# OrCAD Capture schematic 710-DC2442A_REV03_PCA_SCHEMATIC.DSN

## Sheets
1 PAGE4: note: LOW STRESS STAGED START 200A HOT SWAP CONTROLLER
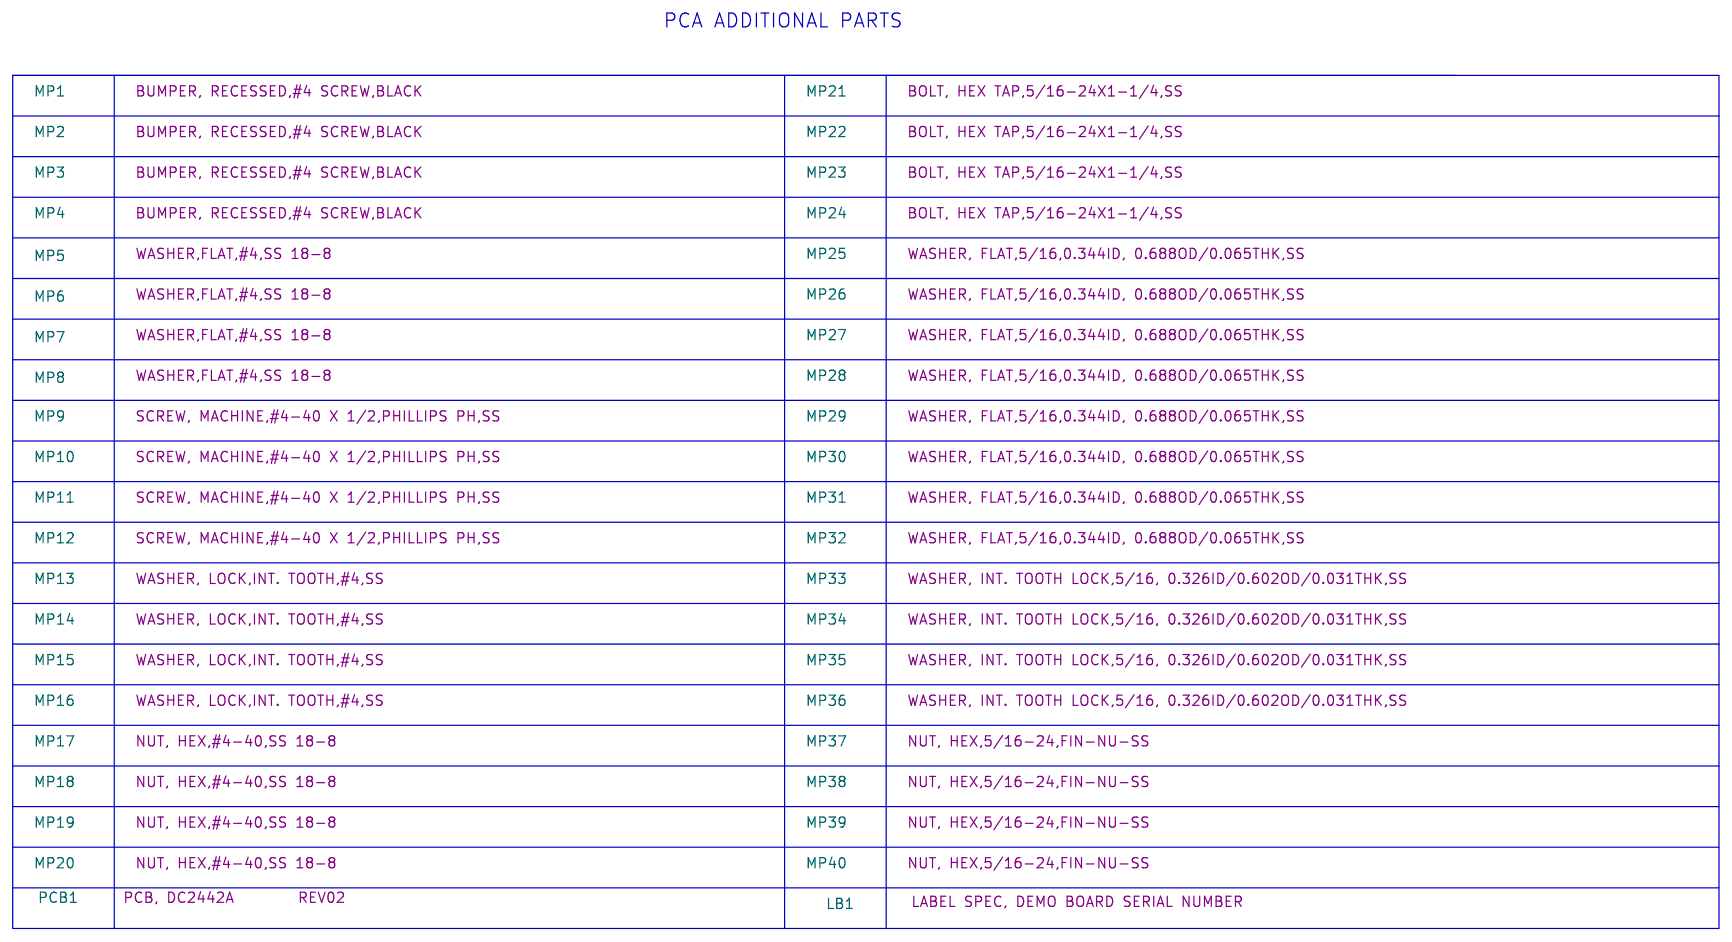
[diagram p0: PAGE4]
2 PAGE3: size Custom
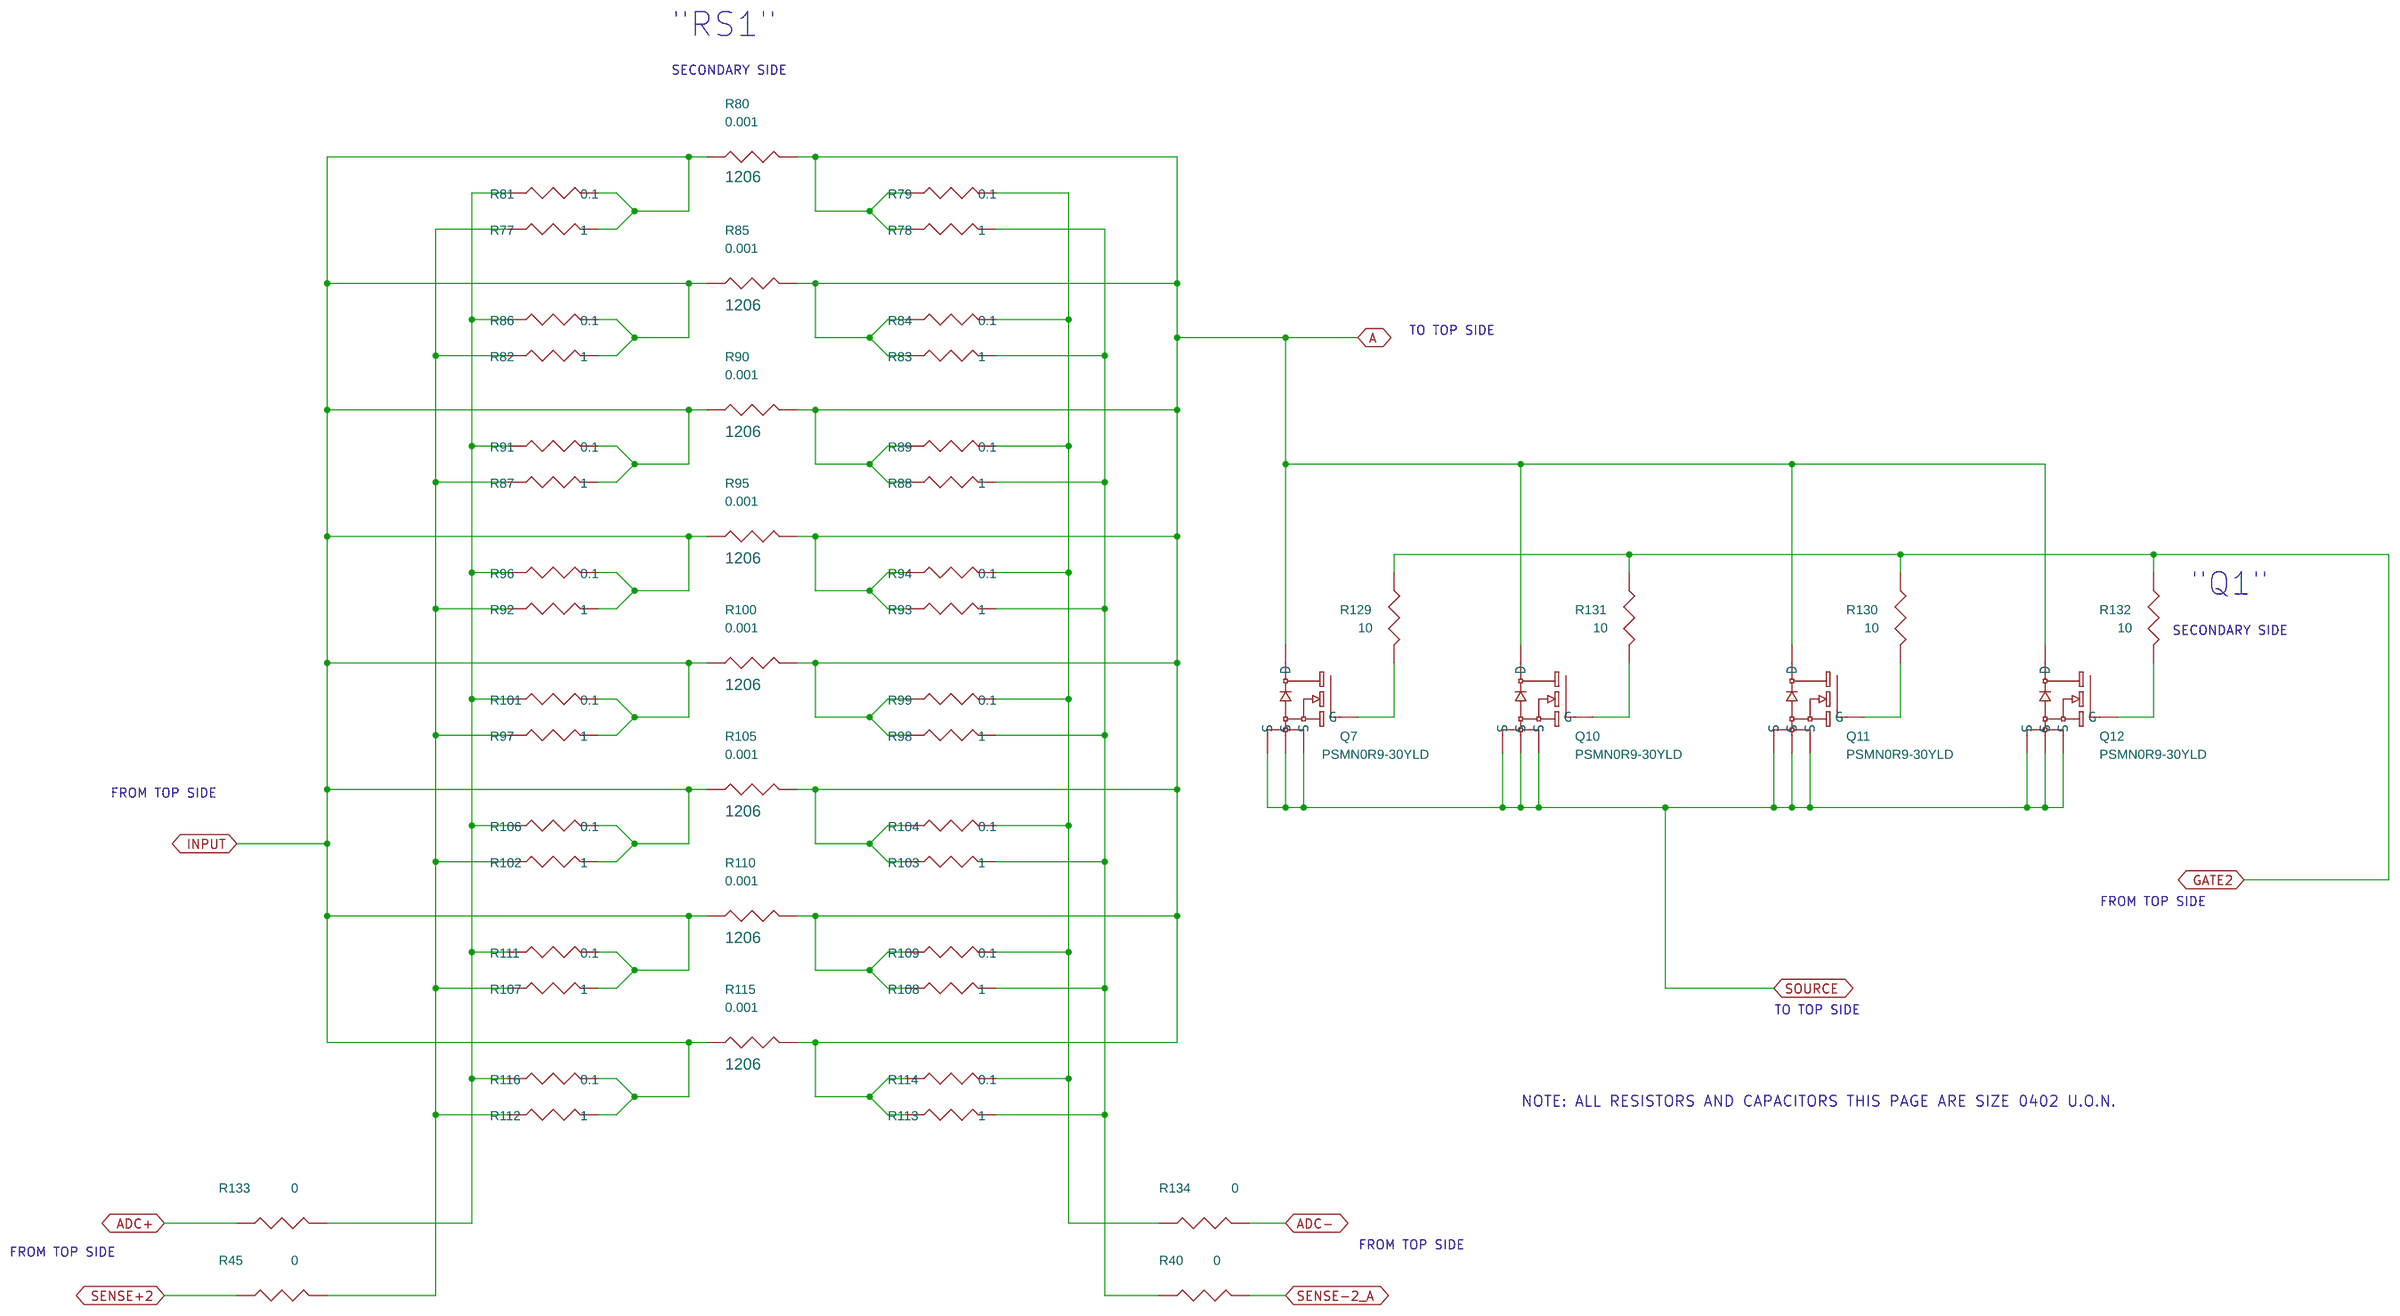
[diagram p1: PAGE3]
3 PAGE1: size Custom
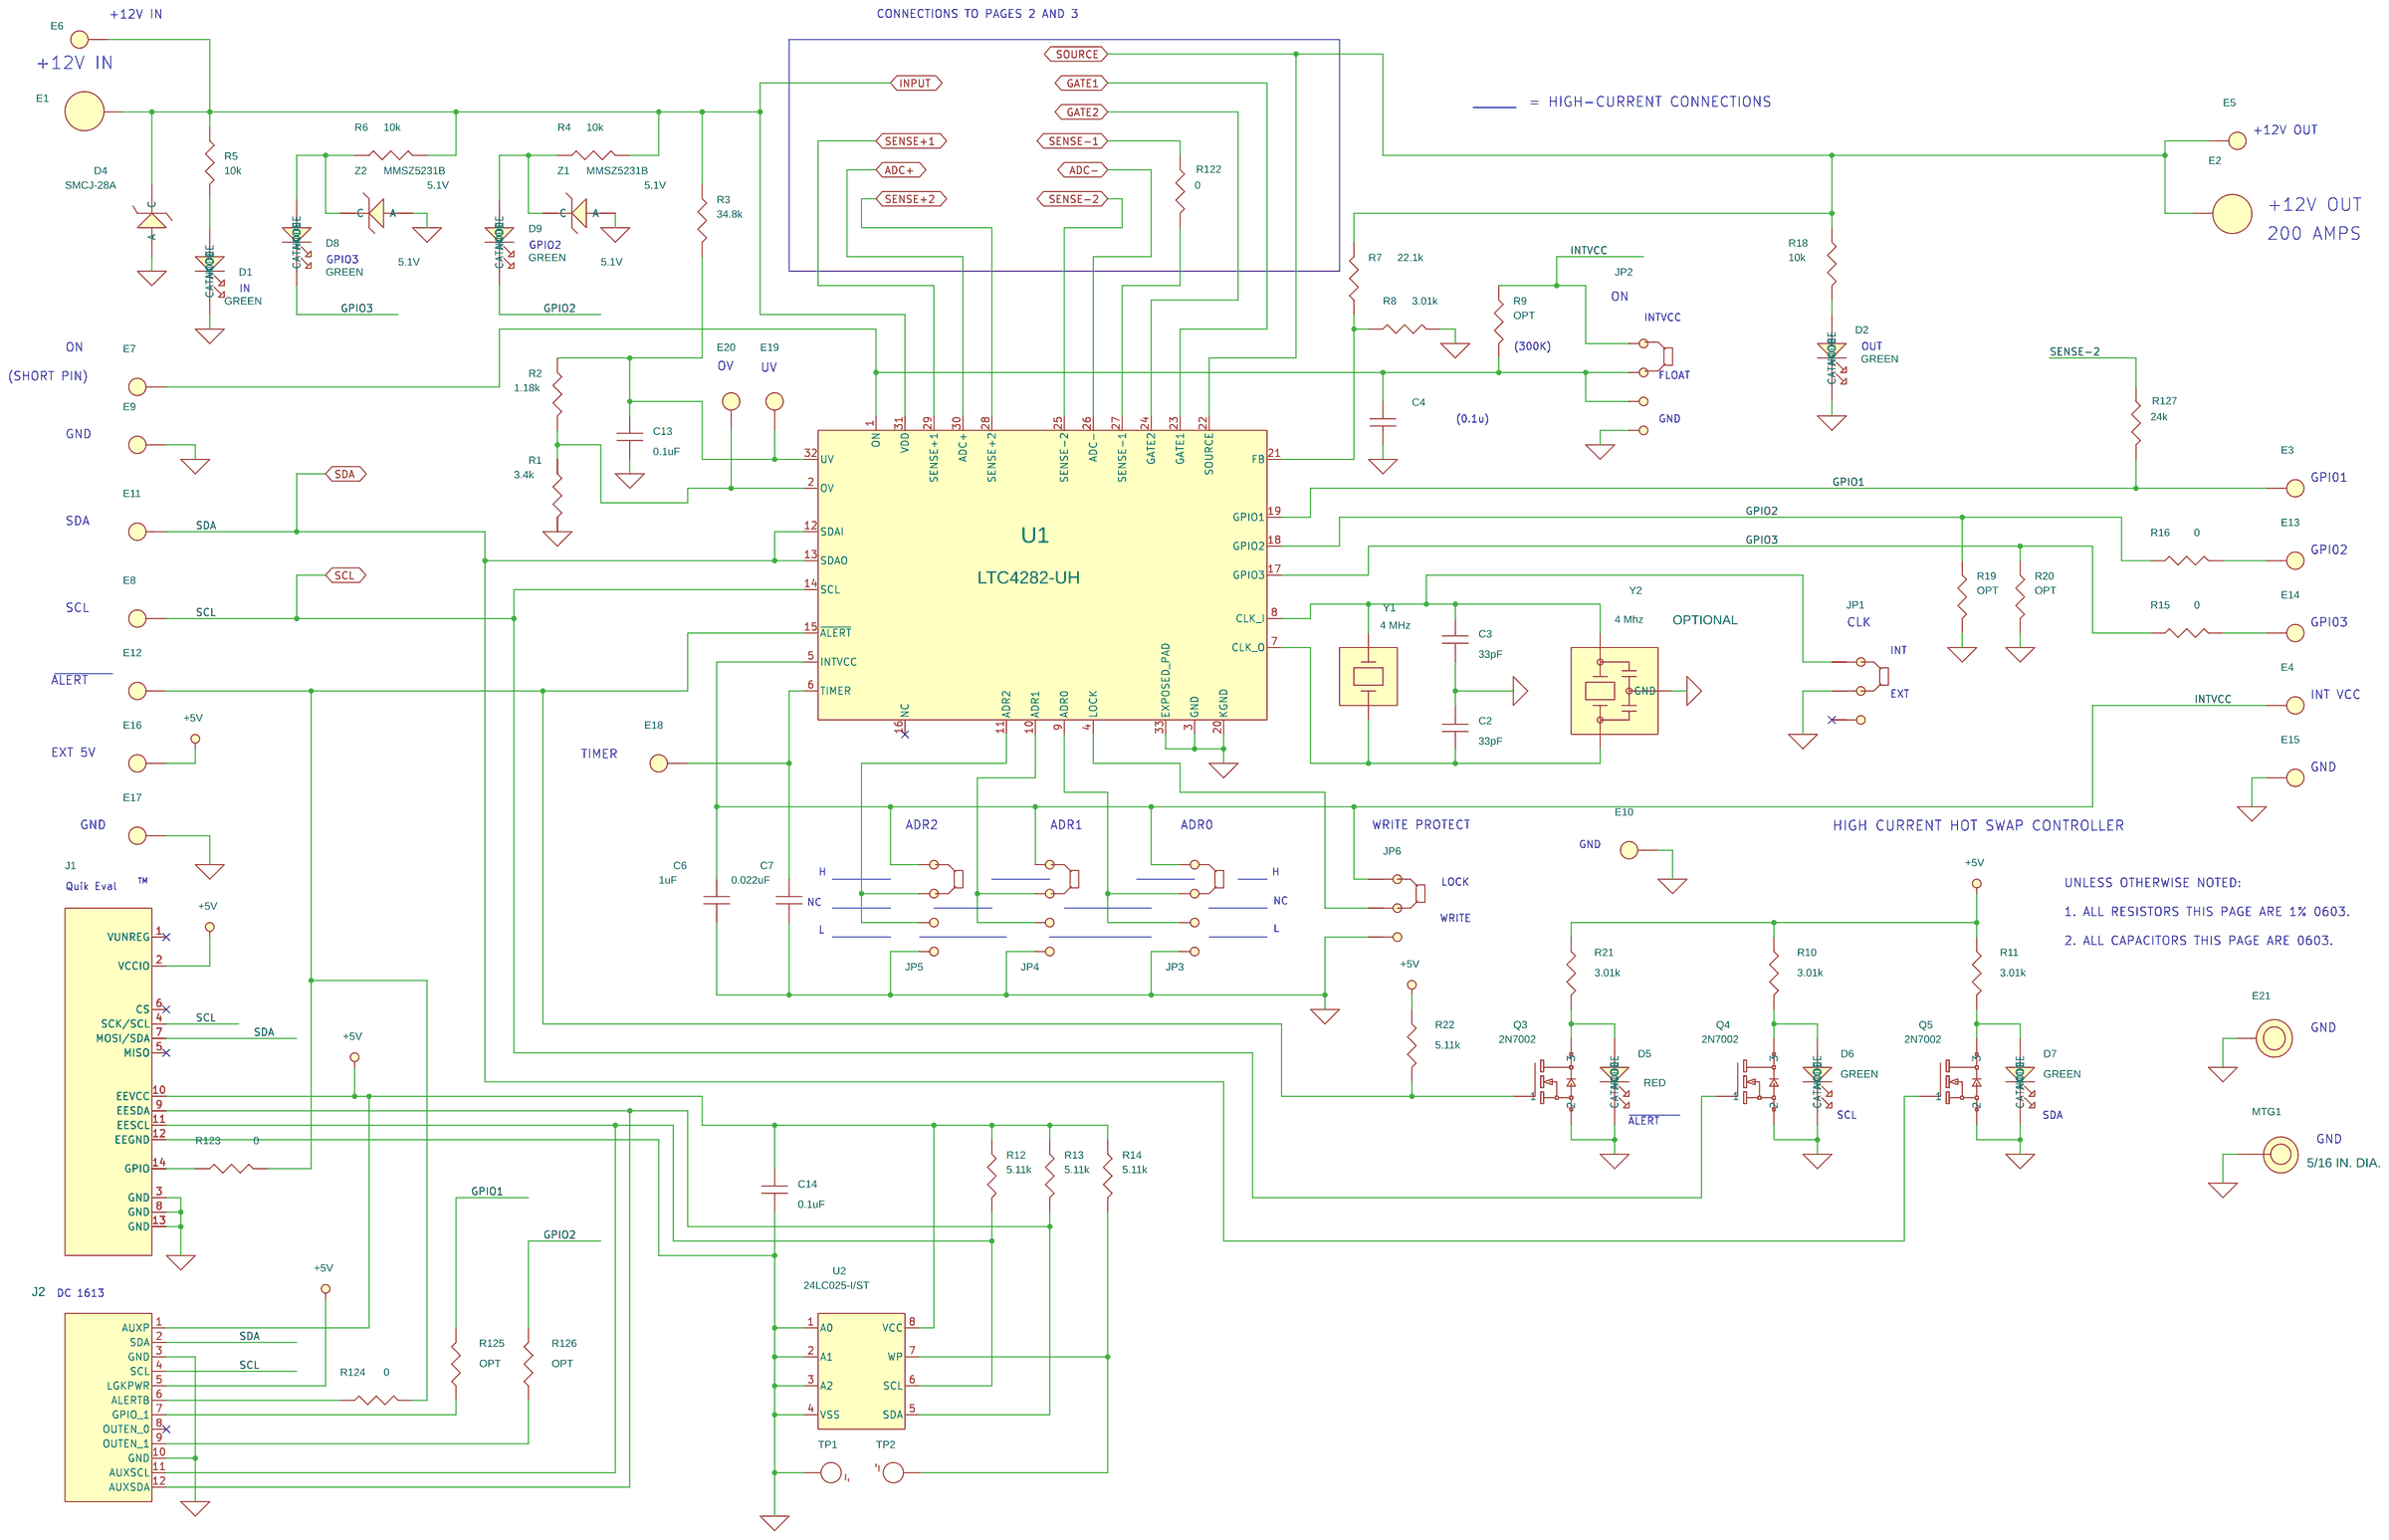
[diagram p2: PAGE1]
4 PAGE2: size Custom
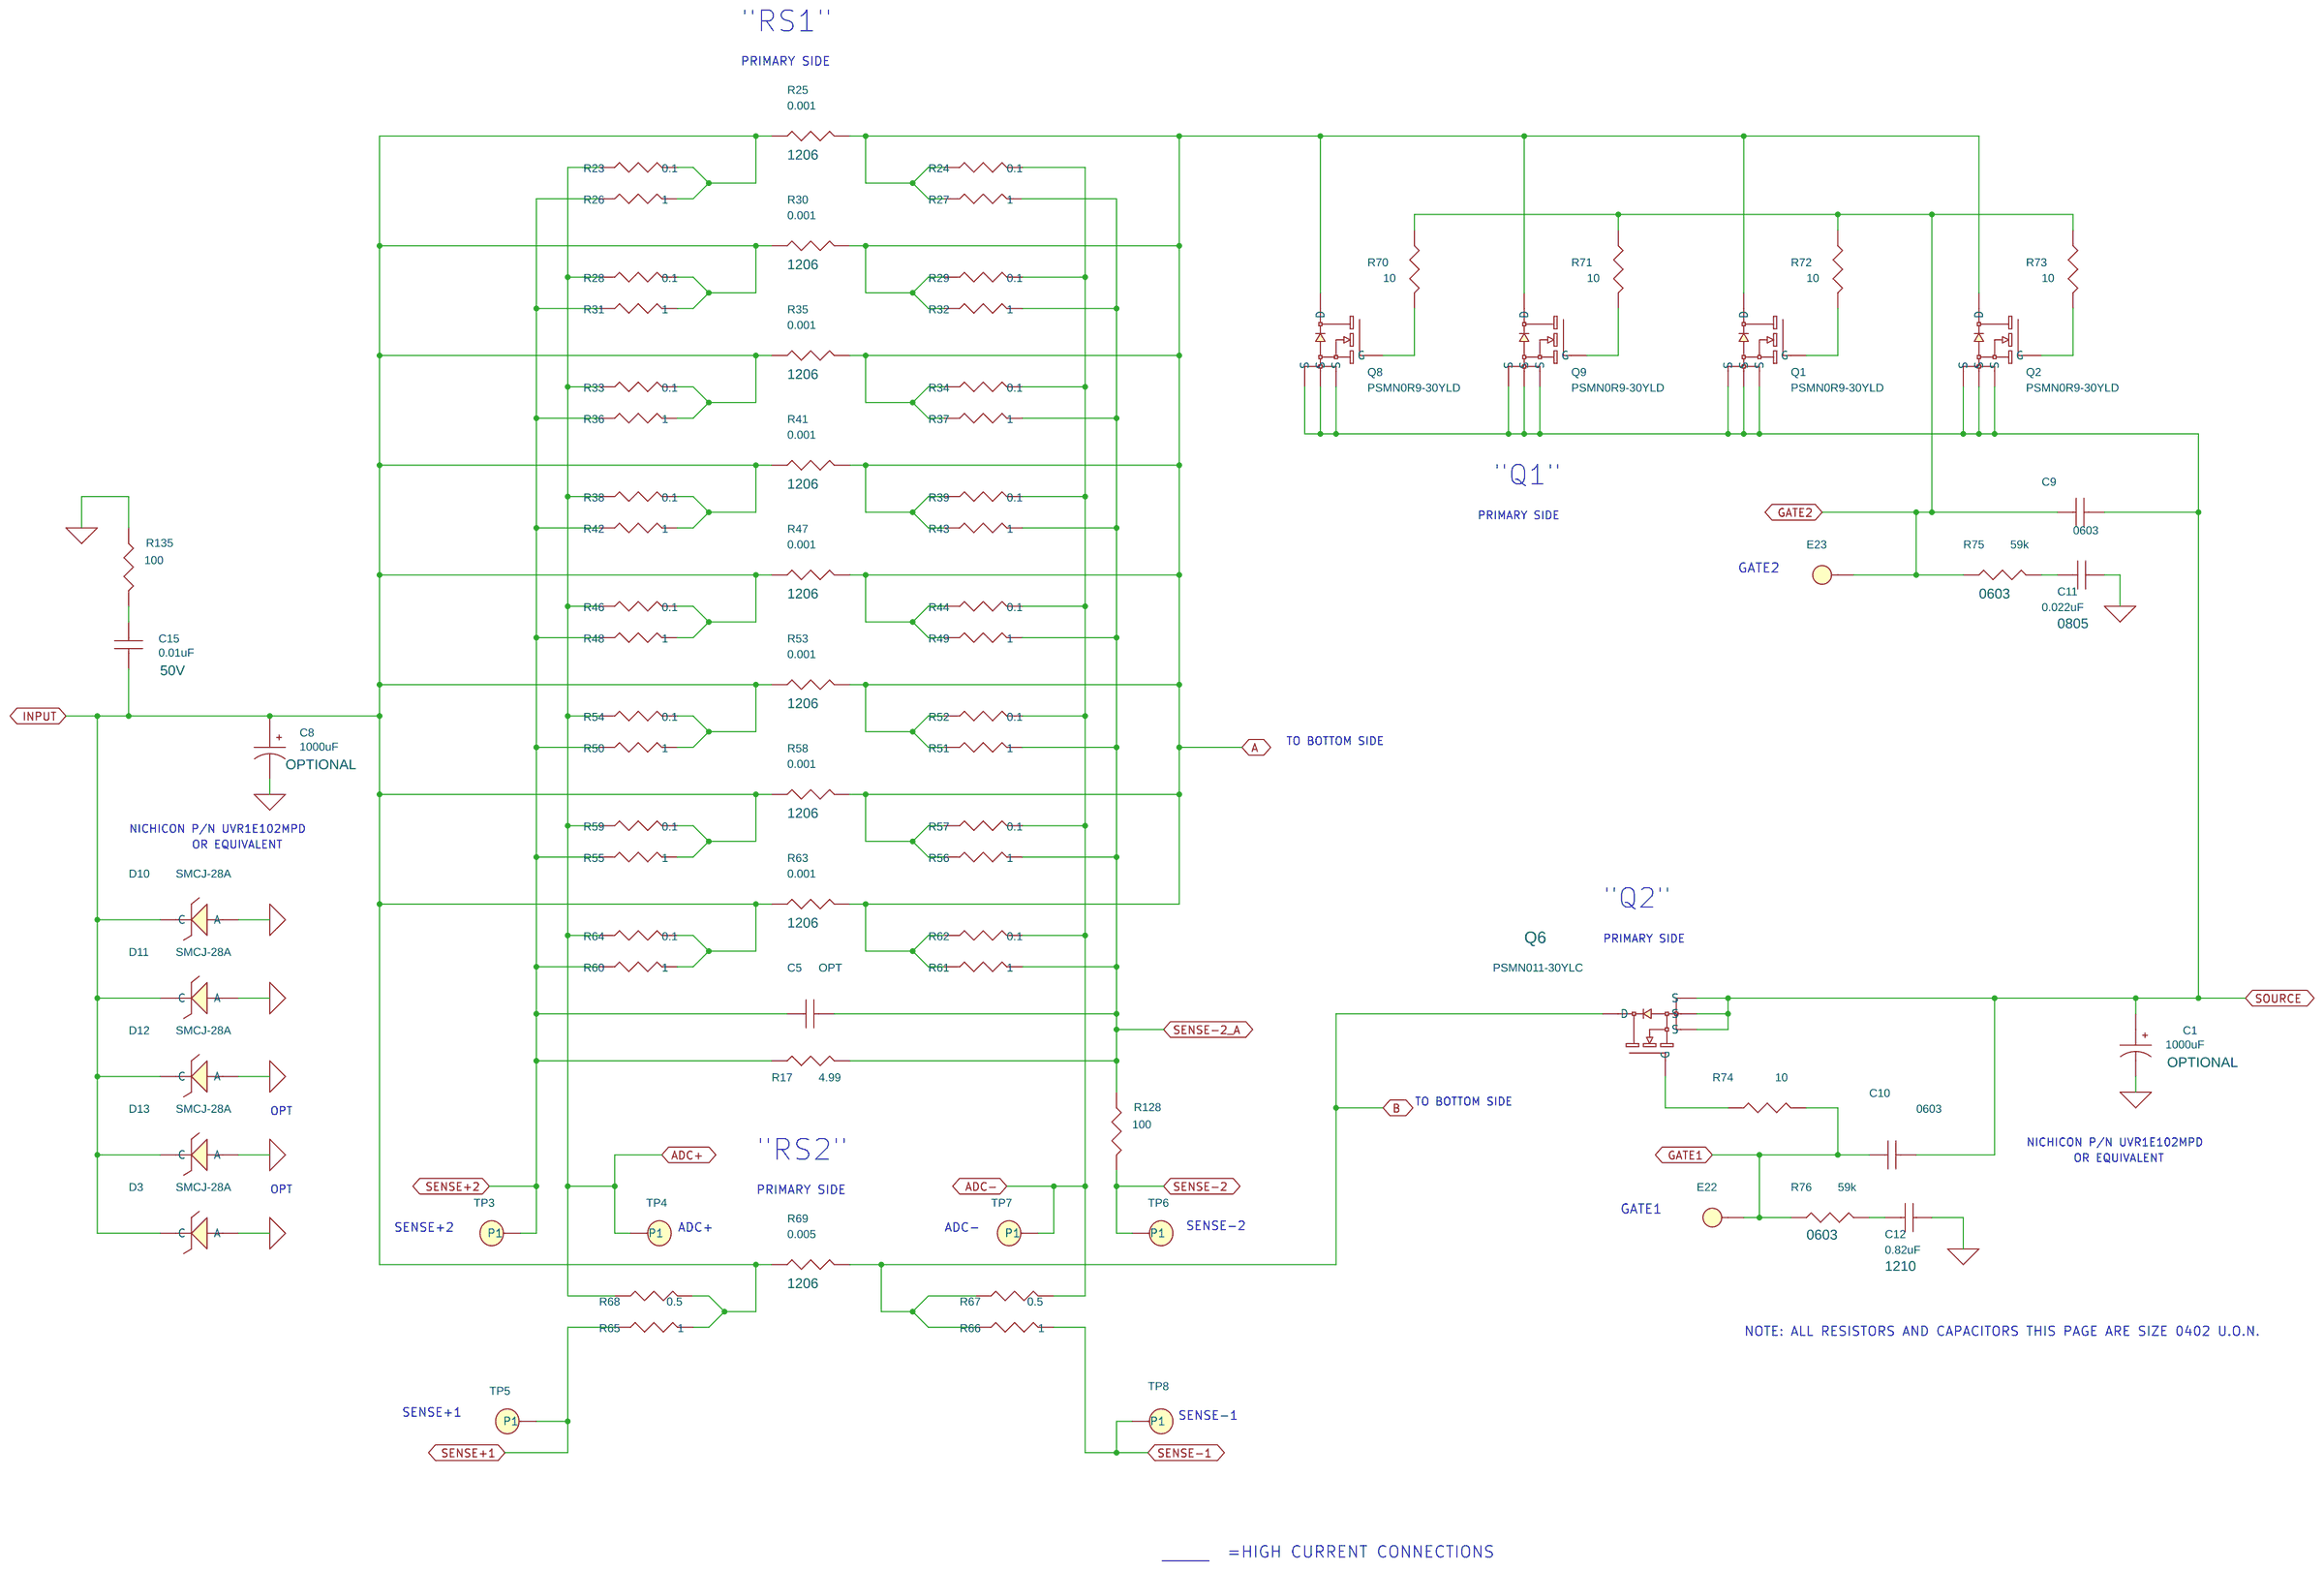
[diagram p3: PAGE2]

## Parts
sheet PAGE1
C2  33pF  [CC0603N]
C3  33pF  [CC0603N]
C4  OPT  [CC0603N]
C6  1uF  [CC0603N]
C7  0.022uF  [CC0603N]
C13  0.1uF  [CC0603N]
C14  0.1uF  [CC0603N]
D1  GREEN  [LED_0805]
D2  GREEN  [LED_0805]
D4  SMCJ-28A  [DIODESINC-SMC]
D5  RED  [LED_0805]
D6  GREEN  [LED_0805]
D7  GREEN  [LED_0805]
D8  GREEN  [LED_0805]
D9  GREEN  [LED_0805]
E1  LUG  [CO225-56HK-QY]
E2  LUG  [CO225-56HK-QY]
E3  TEST POINT  [MILLMAX2308]
E4  TEST POINT  [MILLMAX2308]
E5  TEST POINT  [MILLMAX2308]
E6  TEST POINT  [MILLMAX2308]
E7  TEST POINT  [MILLMAX2308]
E8  TEST POINT  [MILLMAX2308]
E9  TEST POINT  [MILLMAX2308]
E10  TEST POINT  [MILLMAX2308]
E11  TEST POINT  [MILLMAX2308]
E12  TEST POINT  [MILLMAX2308]
E13  TEST POINT  [MILLMAX2308]
E14  TEST POINT  [MILLMAX2308]
E15  TEST POINT  [MILLMAX2308]
E16  TEST POINT  [MILLMAX2308]
E17  TEST POINT  [MILLMAX2308]
E18  TEST POINT  [MILLMAX2308]
E19  TEST POINT  [MILLMAX2308]
E20  TEST POINT  [MILLMAX2308]
E21  BANANA JACK  [KEY-575-4]
J1  HDR.  [HD2X7-079-MOLEX]
J2  HDR, SHROUDED  [HD2X6-079-MOLEX]
JP1  HDR.  [JP3X1/079]
JP2  HDR.  [JP4X1/079]
JP3  HDR.  [JP4X1/079]
JP4  HDR.  [JP4X1/079]
JP5  HDR.  [JP4X1/079]
JP6  HDR.  [JP3X1/079]
MTG1  MTG HOLE  [MTG_5/16]
Q3  2N7002  [SOT23-3N]
Q4  2N7002  [SOT23-3N]
Q5  2N7002  [SOT23-3N]
R1  3.4k  [CR0603N]
R2  1.18k  [CR0603N]
R3  34.8k  [CR0603N]
R4  10k  [CR1206N]
R5  10k  [CR1206N]
R6  10k  [CR1206N]
R7  22.1k  [CR0603N]
R8  3.01k  [CR0603N]
R9  OPT  [CR0603N]
R10  3.01k  [CR0603N]
R11  3.01k  [CR0603N]
R12  5.11k  [CR0603N]
R13  5.11k  [CR0603N]
R14  5.11k  [CR0603N]
R15  0  [CR0603N]
R16  0  [CR0603N]
R18  10k  [CR1206N]
R19  OPT  [CR0603N]
R20  OPT  [CR0603N]
R21  3.01k  [CR0603N]
R22  5.11k  [CR0603N]
R122  0  [CR0603N]
R123  0  [CR0603N]
R124  0  [CR0603N]
R125  OPT  [CR0603N]
R126  OPT  [CR0603N]
R127  24k  [CR0603N]
TP1  TEST PAD  [PADSTYLE6]
TP2  TEST PAD  [PADSTYLE6]
U1  LTC4282-UH  [LTC-UH-32-1693]
U2  24LC025-I/ST  [MICROCHIP-TSSOP-8]
XJP1  SHUNT
XJP2  SHUNT
XJP3  SHUNT
XJP4  SHUNT
XJP5  SHUNT
XJP6  SHUNT
Y1  4 MHz  [ABRACON-ABLS]
Y2  4 Mhz  [MURATA-CSTCR_G]
Z1  MMSZ5231B  [SOD-123N]
Z2  MMSZ5231B  [SOD-123N]
sheet PAGE2
C1  1000uF  [CAPRD10H20LS5]
C5  OPT  [CC0402N]
C8  1000uF  [CAPRD10H20LS5]
C9  OPT  [CC0603N]
C10  OPT  [CC0603N]
C11  0.022uF  [CC0805N]
C12  0.82uF  [CC1210N]
C15  0.01uF  [CC0603N]
D3  SMCJ-28A  [DIODESINC-SMC]
D10  SMCJ-28A  [DIODESINC-SMC]
D11  SMCJ-28A  [DIODESINC-SMC]
D12  SMCJ-28A  [DIODESINC-SMC]
D13  SMCJ-28A  [DIODESINC-SMC]
E22  TEST POINT  [MILLMAX2308]
E23  TEST POINT  [MILLMAX2308]
Q1  PSMN0R9-30YLD  [NXP-LFPAK56]
Q2  PSMN0R9-30YLD  [NXP-LFPAK56]
Q6  PSMN011-30YLC  [NXP-LFPAK(SOT669)]
Q8  PSMN0R9-30YLD  [NXP-LFPAK56]
Q9  PSMN0R9-30YLD  [NXP-LFPAK56]
R17  4.99  [CR0402N]
R23  0.1  [CR0402N]
R24  0.1  [CR0402N]
R25  0.001  [VISHAY_WSL1206]
R26  1  [CR0402N]
R27  1  [CR0402N]
R28  0.1  [CR0402N]
R29  0.1  [CR0402N]
R30  0.001  [VISHAY_WSL1206]
R31  1  [CR0402N]
R32  1  [CR0402N]
R33  0.1  [CR0402N]
R34  0.1  [CR0402N]
R35  0.001  [VISHAY_WSL1206]
R36  1  [CR0402N]
R37  1  [CR0402N]
R38  0.1  [CR0402N]
R39  0.1  [CR0402N]
R41  0.001  [VISHAY_WSL1206]
R42  1  [CR0402N]
R43  1  [CR0402N]
R44  0.1  [CR0402N]
R46  0.1  [CR0402N]
R47  0.001  [VISHAY_WSL1206]
R48  1  [CR0402N]
R49  1  [CR0402N]
R50  1  [CR0402N]
R51  1  [CR0402N]
R52  0.1  [CR0402N]
R53  0.001  [VISHAY_WSL1206]
R54  0.1  [CR0402N]
R55  1  [CR0402N]
R56  1  [CR0402N]
R57  0.1  [CR0402N]
R58  0.001  [VISHAY_WSL1206]
R59  0.1  [CR0402N]
R60  1  [CR0402N]
R61  1  [CR0402N]
R62  0.1  [CR0402N]
R63  0.001  [VISHAY_WSL1206]
R64  0.1  [CR0402N]
R65  1  [CR0402N]
R66  1  [CR0402N]
R67  0.5  [CR0402N]
R68  0.5  [CR0402N]
R69  0.005  [VISHAY_WSL1206]
R70  10  [CR0402N]
R71  10  [CR0402N]
R72  10  [CR0402N]
R73  10  [CR0402N]
R74  10  [CR0402N]
R75  59k  [CR0603N]
R76  59k  [CR0603N]
R128  100  [CR0402N]
R135  100  [CR0603N]
TP3  TEST PAD  [PADSTYLE2]
TP4  TEST PAD  [PADSTYLE2]
TP5  TEST PAD  [PADSTYLE2]
TP6  TEST PAD  [PADSTYLE2]
TP7  TEST PAD  [PADSTYLE2]
TP8  TEST PAD  [PADSTYLE2]
sheet PAGE3
Q7  PSMN0R9-30YLD  [NXP-LFPAK56]
Q10  PSMN0R9-30YLD  [NXP-LFPAK56]
Q11  PSMN0R9-30YLD  [NXP-LFPAK56]
Q12  PSMN0R9-30YLD  [NXP-LFPAK56]
R40  0  [CR0402N]
R45  0  [CR0402N]
R77  1  [CR0402N]
R78  1  [CR0402N]
R79  0.1  [CR0402N]
R80  0.001  [VISHAY_WSL1206]
R81  0.1  [CR0402N]
R82  1  [CR0402N]
R83  1  [CR0402N]
R84  0.1  [CR0402N]
R85  0.001  [VISHAY_WSL1206]
R86  0.1  [CR0402N]
R87  1  [CR0402N]
R88  1  [CR0402N]
R89  0.1  [CR0402N]
R90  0.001  [VISHAY_WSL1206]
R91  0.1  [CR0402N]
R92  1  [CR0402N]
R93  1  [CR0402N]
R94  0.1  [CR0402N]
R95  0.001  [VISHAY_WSL1206]
R96  0.1  [CR0402N]
R97  1  [CR0402N]
R98  1  [CR0402N]
R99  0.1  [CR0402N]
R100  0.001  [VISHAY_WSL1206]
R101  0.1  [CR0402N]
R102  1  [CR0402N]
R103  1  [CR0402N]
R104  0.1  [CR0402N]
R105  0.001  [VISHAY_WSL1206]
R106  0.1  [CR0402N]
R107  1  [CR0402N]
R108  1  [CR0402N]
R109  0.1  [CR0402N]
R110  0.001  [VISHAY_WSL1206]
R111  0.1  [CR0402N]
R112  1  [CR0402N]
R113  1  [CR0402N]
R114  0.1  [CR0402N]
R115  0.001  [VISHAY_WSL1206]
R116  0.1  [CR0402N]
R129  10  [CR0402N]
R130  10  [CR0402N]
R131  10  [CR0402N]
R132  10  [CR0402N]
R133  0  [CR0402N]
R134  0  [CR0402N]
sheet PAGE4
LB1  LABEL  [895-0154_REV01]
MP1  BUMPER, RECESSED
MP2  BUMPER, RECESSED
MP3  BUMPER, RECESSED
MP4  BUMPER, RECESSED
MP5  WASHER
MP6  WASHER
MP7  WASHER
MP8  WASHER
MP9  SCREW, MACHINE
MP10  SCREW, MACHINE
MP11  SCREW, MACHINE
MP12  SCREW, MACHINE
MP13  WASHER, LOCK
MP14  WASHER, LOCK
MP15  WASHER, LOCK
MP16  WASHER, LOCK
MP17  NUT, HEX
MP18  NUT, HEX
MP19  NUT, HEX
MP20  NUT, HEX
MP21  BOLT, HEX TAP
MP22  BOLT, HEX TAP
MP23  BOLT, HEX TAP
MP24  BOLT, HEX TAP
MP25  WASHER, FLAT
MP26  WASHER, FLAT
MP27  WASHER, FLAT
MP28  WASHER, FLAT
MP29  WASHER, FLAT
MP30  WASHER, FLAT
MP31  WASHER, FLAT
MP32  WASHER, FLAT
MP33  WASHER, INT. TOOTH LOCK
MP34  WASHER, INT. TOOTH LOCK
MP35  WASHER, INT. TOOTH LOCK
MP36  WASHER, INT. TOOTH LOCK
MP37  NUT, HEX
MP38  NUT, HEX
MP39  NUT, HEX
MP40  NUT, HEX
PCB1  PCB, DC2442A

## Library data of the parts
C2 C3 = CAP: CAP.,33pF,X7R,16V,5%,0603; CLASS: DISCRETE; Dielectric Type: X7R; Manufacturer: AVX; Manufacturer PN: 0603YC330JAT2A; PART_NUMBER: 150-2014; Package Size: 0603; Package Type: SMD; Rated Voltage: 16V; Tolerance: 5%
C4 C9 C10 = CAP: CAP., OPTION, 0603; CLASS: DISCRETE; FPLIST: CC0603N,CC0603L,CC0603M; PART_NUMBER: 150-3038; Package Size: 0603; Package Type: SMD; UserField01: OPTION
C6 = CAP: CAP.,1uF,X7R,16V,10%,0603; CLASS: DISCRETE; Dielectric Type: X7R; Manufacturer: AVX; Manufacturer PN: 0603YC105KAT2A; PART_NUMBER: 150-3384; Package Size: 0603; Package Type: SMD; Rated Voltage: 16V; Tolerance: 10%
C7 = CAP: CAP.,0.022uF,X7R,16V,10%,0603; CLASS: DISCRETE; Dielectric Type: X7R; FPLIST: CC0603N,CC0603L,CC0603M; Manufacturer: MURATA; Manufacturer PN: GRM188R71C223KA01D; PART_NUMBER: 150-3074; Package Size: 0603; Rated Voltage: 16V; Tolerance: 10%
C13 = CAP: CAP.,0.1uF,X7R,25V,20%,0603; CLASS: DISCRETE; Dielectric Type: X7R; Manufacturer: MURATA; Manufacturer PN: GRM188R71E104MA01D; PART_NUMBER: 150-3402; Package Size: 0603; Package Type: SMD; Rated Voltage: 25V; Tolerance: 20%
C14 = CAP: CAP.,0.1uF,X7R,16V,10%,0603; CLASS: DISCRETE; Dielectric Type: X7R; Manufacturer: AVX; Manufacturer PN: 0603YC104KAT2A; PART_NUMBER: 150-0164; Package Size: 0603; Package Type: SMD; Rated Voltage: 16V; Tolerance: 10%
D1 D2 D6-D9 = LED: LED,GREEN,WATERCLEAR,0805; CLASS: DISCRETE; FPLIST: LED_0805,WURTH_LED_0805; Manufacturer: WURTH ELEKTRONIK; Manufacturer PN: 150080GS75000; PART_NUMBER: 270-0063; Package Size: 0805; Package Type: 0805
D3 D4 D10-D13 = DIODE_TVS_B: DIODE,TVS,28V,1500W,SMC; CLASS: DISCRETE; Manufacturer: DIODES INC.; Manufacturer PN: SMCJ28A-13-F; PART_NUMBER: 210-0182; Package Size: SMC; Package Type: SMC; Rated Voltage: 28V
D5 = LED: LED,RED,CLEAR,0805; CLASS: DISCRETE; Manufacturer: WURTH ELEKTRONIK; Manufacturer PN: 150080RS75000; PART_NUMBER: 270-0081; Package Type: 0805
E1 E2 = TONGUE_LUG: LUG,COPPER,2 HOLE; CLASS: MECHANICAL PART; Manufacturer: PENCOM; Manufacturer PN: EL1668; PART_NUMBER: 769-0009
E3-E20 E22 E23 = TEST_POINT_.156_MILL-MAX_2308: TEST POINT,TURRET,0.064" MTG. HOLE,0.125" THICK PCB; CLASS: IO; Manufacturer: MILL-MAX; Manufacturer PN: 2308-4-00-80-00-00-07-0; PART_NUMBER: 260-0008
E21 = BANANA_KEYSTONE-575-4: CONN.,BANANA JACK,FEMALE,THT,NON-INSULATED, SWAGE; CLASS: IO; Manufacturer: KEYSTONE; Manufacturer PN: 575-4; PART_NUMBER: 250-0428
J1 = CONN_2X7_.079_MOLEX_RIBBON_A: CONN.,HDR.,MALE,2x7,2mm,THT, VERT,SHROUDED; CLASS: IO; Manufacturer: MOLEX; Manufacturer PN: 87831-1420; PART_NUMBER: 250-0403
J2 = CONN._FCI_12_POS_2MM: CONN.,HDR, SHROUDED,2x6,2mm,THT, VERT; CLASS: IO; Manufacturer: FCI; Manufacturer PN: 98414-G06-12ULF; PART_NUMBER: 250-0433
JP1 JP6 = HDR3X1_B: CONN.,HDR.,MALE,1x3,2mm,THT, STR; CLASS: IO; Manufacturer: SAMTEC; Manufacturer PN: TMM-103-02-L-S; PART_NUMBER: 250-0422
JP2-JP5 = 4_PIN_HEADER_.079_SINGLE_ROW_C: CONN.,HDR.,MALE,1x4,2mm,THT, STR; CLASS: IO; Manufacturer: SAMTEC; Manufacturer PN: TMM-104-02-L-S; PART_NUMBER: 250-0441
MTG1 = MTG_STYLE_B: PCB MOUNTING HOLE; BOM Notes: 5/16 IN. DIA.; CLASS: IO; PART_NUMBER: PCBPADS-13
Q3-Q5 = 2N7002_SOT-23: XSTR.,MOSFET N-CH,60V,300mA,SOT-23; CLASS: DISCRETE; Manufacturer: VISHAY; Manufacturer PN: 2N7002K-T1-GE3; PART_NUMBER: 240-0125; Package Size: SOT-23; Package Type: SOT-23; Rated Voltage: 60V
R1 = RES: RES.,3.4k OHMS,1%,1/10W,0603; CLASS: DISCRETE; Manufacturer: NIC; Manufacturer PN: NRC06F3741TRF; PART_NUMBER: 100-2782; Package Size: 0603; Rated Power: 1/10W; Temperature Coefficient: 100ppm/C; Tolerance: 1%
R2 = RES: RES.,1.18k OHMS,1%,1/10W,0603; CLASS: DISCRETE; Manufacturer: YAGEO; Manufacturer PN: RC0603FR-071K18L; PART_NUMBER: 100-2015; Package Size: 0603; Rated Power: 1/10W; Temperature Coefficient: +/-100 PPM; Tolerance: 1%
R3 = RES: RES.,34.8k OHMS,1%,1/10W,0603; CLASS: DISCRETE; Manufacturer: VISHAY; Manufacturer PN: CRCW060334K8FKEA; PART_NUMBER: 100-2669; Package Size: 0603; Rated Power: 1/10W; Temperature Coefficient: 100ppm/C; Tolerance: 1%
R4-R6 R18 = RES: RES.,10k OHMS,5%,1/4W,1206; CLASS: DISCRETE; Manufacturer: PANASONIC; Manufacturer PN: ERJ8GEYJ103V; PART_NUMBER: 100-0317; Package Size: 1206; Rated Power: 1/4W; Temperature Coefficient: 200ppm; Tolerance: 5%
R7 = RES: RES.,22.1k OHMS,1%,1/10W,0603; CLASS: DISCRETE; Manufacturer: NIC; Manufacturer PN: NRC06F2212TRF; PART_NUMBER: 100-2448; Package Size: 0603; Rated Power: 1/10W; Temperature Coefficient: 100ppm/C; Tolerance: 1%
R8 R10 R11 R21 = RES: RES.,3.01k OHMS,1%,1/10W,0603; CLASS: DISCRETE; Manufacturer: VISHAY; Manufacturer PN: CRCW06033K01FKEA; PART_NUMBER: 100-2477; Package Size: 0603; Rated Power: 1/10W; Temperature Coefficient: 100ppm/C; Tolerance: 1%
R9 R19 R20 R125 R126 = RES: RES., OPTION, 0603; CLASS: DISCRETE; FPLIST: CR0603N,CR0603L,CR0603M; PART_NUMBER: 100-2374; Package Size: 0603
R12-R14 R22 = RES: RES.,5.11k OHMS,1%,1/10W,0603; CLASS: DISCRETE; Manufacturer: PANASONIC; Manufacturer PN: ERJ3EKF5111V; PART_NUMBER: 100-2603; Package Size: 0603; Rated Power: 1/10W; Temperature Coefficient: 100ppm/C; Tolerance: 1%
R15 R16 R122-R124 = RES: RES.,0 OHM,1/10W,0603; CLASS: DISCRETE; Manufacturer: VISHAY; Manufacturer PN: CRCW06030000Z0EA; PART_NUMBER: 100-0009; Package Size: 0603; Rated Power: 1/10W
R127 = RES: RES.,24k OHMS,5%,1/10W,0603; CLASS: DISCRETE; Manufacturer: VISHAY; Manufacturer PN: CRCW060324K0JNEA; PART_NUMBER: 100-0456; Package Size: 0603; Rated Power: 1/10W; Temperature Coefficient: 200ppm; Tolerance: 5%
TP1 TP2 = TESTPOINT_FILLED_CIRCLE: TESTPOINT, PCB COPPER FEATURE; CLASS: IO; FPLIST: PADSTYLE1,PADSTYLE2,PADSTYLE3,PADSTYLE4,PADSTYLE5,PADSTYLE6,PADSTYLE7,PADSTYLE8; Manufacturer: N/A; Manufacturer PN: N/A; PART_NUMBER: PCBPADS-1
U1 = LTC4282-UH: IC,Hi-Current Hot Swap Controller,QFN-32; CLASS: IC; Manufacturer: LINEAR TECHNOLOGY; Manufacturer PN: LTC4282IUH#PBF; PART_NUMBER: LTC4282IUH#PBF; Package Size: UH-32; Package Type: QFN-32; Part Number: LINEAR TECH., LTC4282CUH#PBF
U2 = 24LC025-I_ST_TSSOP-8: IC, MEMORY,EEPROM,2Kb (256x8),TSSOP-8,400kHz; CLASS: IC; Manufacturer: Microchip; PART_NUMBER: 380-0087; Package Size: TSSOP-8; Package Type: TSSOP-8
XJP1-XJP6 = SHUNT_2MM: CONN.,SHUNT,FEMALE,2 POS,2mm; CLASS: IO; Manufacturer: SAMTEC; Manufacturer PN: 2SN-BK-G; PART_NUMBER: 250-0419
Y1 = XTAL_4MHZ_ABLS: CRYSTAL,4 MHz,18pF,+/-50ppm Stability,11.5x4.7x4.2mm, 2Pad SMD,+/-30ppm Tolerance; CLASS: DISCRETE; Frequency Stability: +/-50ppm Stability; Manufacturer: ABRACON CORPORATION; Manufacturer PN: ABLS-4.000MHZ-B4-T; PART_NUMBER: 340-0072
Y2 = RESONATOR: RESONATOR, 4Mhz, SMT, OPTION; BOM Notes: OPTIONAL; CLASS: DISCRETE; PART_NUMBER: TMP-1704
Z1 Z2 = ZENER: DIODE,ZENER,5.1V,500mW,SOD-123; CLASS: DISCRETE; Manufacturer: FAIRCHILD; PART_NUMBER: 210-0183; Package Size: SOD-123; Package Type: SOD-123; Rated Voltage: 5.1V; Vz: 5.1V
C1 C8 = CAP_P: CAP ALUM 1000UF 25V 20% RADIAL; BOM Notes: OPTIONAL; CLASS: DISCRETE; Dielectric Type: Capacitors; Manufacturer: Nichicon; Manufacturer PN: UVR1E102MPD; PART_NUMBER: TMP-918; Package Size: Radial, Can; Package Type: Through Hole; Rated Voltage: 25V; Tolerance: 20%
C5 = CAP: CAP., OPTION, 0402; CLASS: DISCRETE; PART_NUMBER: 150-3148; Package Size: 0402; Package Type: SMD
C11 = CAP: CAP.,0.022uF,X7R,50V,5%,0805; CLASS: DISCRETE; Dielectric Type: X7R; FPLIST: CC0805N,CC0805L,CC0805M; Manufacturer: Kemet; Manufacturer PN: C0805C223J5RACTU; PART_NUMBER: 150-2016; Package Size: 0805; Package Type: Surface Mount, MLCC; Rated Voltage: 50V; Tolerance: 5%
C12 = CAP: CAP.,0.82uF,X7R,50V,10%,1210; CLASS: DISCRETE; Dielectric Type: X7R; FPLIST: CC1210N,CC1210L,CC1210M; Manufacturer: MURATA; Manufacturer PN: GRM32RR71H824KA01L; PART_NUMBER: 150-2227; Package Size: 1210; Package Type: Surface Mount, MLCC; Rated Voltage: 50V; Tolerance: 10%
C15 = CAP: CAP.,0.01uF,X7R,50V,10%,0603; CLASS: DISCRETE; Dielectric Type: X7R; FPLIST: CC0603N,CC0603L,CC0603M; Manufacturer: KEMET; Manufacturer PN: C0603C103K5RAC7867; PART_NUMBER: 150-0002; Package Size: 0603; Rated Voltage: 50V; Tolerance: 10%
Q1 Q2 Q7-Q12 = PSMN0R9-30YLD: XSTR.,MOSFET, N-CH,30V,300A,LFPAK56, Power-SO8; CLASS: DISCRETE; Manufacturer: NXP SEMICONDUCTORS; Manufacturer PN: PSMN0R9-30YLDX; PART_NUMBER: 240-0193; Package Size: LFPAK56; Package Type: LFPAK56, Power-SO8; Rated Voltage: 30V
Q6 = MOSFET_N-CH_C: XSTR.,MOSFET, N-CH,30V,37A,LFPAK, Power-SO8; CLASS: DISCRETE; Manufacturer: NXP Semiconductors; Manufacturer PN: PSMN011-30YLC,115; PART_NUMBER: 240-0194; Package Size: SC-100, SOT-669, 4-LFPAK; Package Type: LFPAK, Power-SO8; Polarity: MOSFET N-Channel, Metal Oxide; Rated Power: 29W; Rated Voltage: 30V
R17 = RES: RES.,4.99 OHMS,1%,1/16W,0402; CLASS: DISCRETE; FPLIST: CR0402N,CR0402L,CR0402M; Manufacturer: VISHAY; Manufacturer PN: CRCW04024R99FKED; PART_NUMBER: 100-0634; Package Size: 0402; Rated Power: 1/16W; Temperature Coefficient: +/-100ppm; Tolerance: 1%
R23 R24 R28 R29 R33 R34 R38 R39 R44 R46 R52 R54 R57 R59 R62 R64 R79 R81 R84 R86 R89 R91 R94 R96 R99 R101 R104 R106 R109 R111 R114 R116 = RES: RES.,SENSE,0.1 OHM,1%,1/16W,0402; CLASS: DISCRETE; FPLIST: CR0402N,CR0402L,CR0402M; Manufacturer: Yageo; Manufacturer PN: RL0402FR-070R1L; PART_NUMBER: 100-0453; Package Size: 0402; Rated Power: 1/16W; Temperature Coefficient: 800ppm; Tolerance: 1%
R25 R30 R35 R41 R47 R53 R58 R63 R80 R85 R90 R95 R100 R105 R110 R115 = RES: RES.,SENSE,0.001 OHM,1%,1/4W,1206; CLASS: DISCRETE; Manufacturer: VISHAY; Manufacturer PN: WSL12061L000FEA; PART_NUMBER: 100-0454; Package Size: 1206; Rated Power: 1/4W; Temperature Coefficient: 275ppm; Tolerance: 1%
R26 R27 R31 R32 R36 R37 R42 R43 R48-R51 R55 R56 R60 R61 R65 R66 R77 R78 R82 R83 R87 R88 R92 R93 R97 R98 R102 R103 R107 R108 R112 R113 = RES: RES.,1 OHM,1%,1/16W,0402; CLASS: DISCRETE; Manufacturer: VISHAY; Manufacturer PN: CRCW04021R00FKED; PART_NUMBER: 100-0241; Package Size: 0402; Rated Power: 1/16W; Temperature Coefficient: 100ppm; Tolerance: 1%
R67 R68 = RES: RES.,SENSE, AEC-Q200,0.5 OHM,1%,1/16W,0402; CLASS: DISCRETE; FPLIST: CR0402N,CR0402L,CR0402M; Manufacturer: YAGEO; Manufacturer PN: RL0402FR-070R5L; PART_NUMBER: 100-0555; Package Size: 0402; Rated Power: 1/16W; Temperature Coefficient: 300ppm; Tolerance: 1%
R69 = RES: RES.,SENSE,0.005 OHM,1%,1/4W,1206; CLASS: DISCRETE; Manufacturer: VISHAY; Manufacturer PN: WSL12065L000FEA; PART_NUMBER: 100-2690; Package Size: 1206; Rated Power: 1/4W; Temperature Coefficient: 110ppm; Tolerance: 1%
R70-R74 R129-R132 = RES: RES.,10 OHMS,1%,1/16W,0402; CLASS: DISCRETE; Manufacturer: YAGEO; Manufacturer PN: RC0402FR-0710RL; PART_NUMBER: 100-0041; Package Size: 0402; Rated Power: 1/16W; Temperature Coefficient: 200ppm/C; Tolerance: 1%
R75 R76 = RES: RES.,59k OHMS,1%,1/10W,0603; CLASS: DISCRETE; FPLIST: CR0603N,CR0603L,CR0603M; Manufacturer: VISHAY; Manufacturer PN: CRCW060359K0FKEA; PART_NUMBER: 100-2121; Package Size: 0603; Rated Power: 1/10W; Temperature Coefficient: +/-100PPM; Tolerance: 1%
R128 = RES: RES.,100 OHMS,1%,1/16W,0402; CLASS: DISCRETE; Manufacturer: NIC; Manufacturer PN: NRC04F1000TRF; PART_NUMBER: 100-2626; Package Size: 0402; Rated Power: 1/16W; Temperature Coefficient: 100ppm/C; Tolerance: 1%
R135 = RES: RES.,100 OHMS,1%,1/10W,0603; CLASS: DISCRETE; FPLIST: CR0603N,CR0603L,CR0603M; Manufacturer: NIC; Manufacturer PN: NRC06F1000TRF; PART_NUMBER: 100-2586; Package Size: 0603; Rated Power: 1/10W; Temperature Coefficient: 100ppm; Tolerance: 1%
TP3-TP8 = PAD_STYLE_D: TESTPOINT, PCB COPPER FEATURE; CLASS: IO; FPLIST: PADSTYLE1,PADSTYLE2,PADSTYLE3,PADSTYLE4,PADSTYLE5,PADSTYLE6,PADSTYLE7,PADSTYLE8; Manufacturer: N/A; Manufacturer PN: N/A; PART_NUMBER: PCBPADS-7
R40 R45 R133 R134 = RES: RES.,0 OHM,1/16W,0402; CLASS: DISCRETE; FPLIST: CR0402N,CR0402L,CR0402M; Manufacturer: NIC; Manufacturer PN: NRC04ZOTRF; PART_NUMBER: 100-0215; Package Size: 0402; Rated Power: 1/16W
LB1 = BLANK_LABEL: LABEL SPEC, DEMO BOARD SERIAL NUMBER; Manufacturer: BRADY; Manufacturer PN: THT-96-717-10; PART_NUMBER: 895-0154
MP1-MP4 = BLANK_PINLESS_MECHANICAL_PART: BUMPER, RECESSED,#4 SCREW,BLACK; CLASS: MECHANICAL PART; Manufacturer: KEYSTONE; Manufacturer PN: 727; PART_NUMBER: 763-0018
MP5-MP8 = BLANK_PINLESS_MECHANICAL_PART: WASHER,FLAT,#4,SS 18-8; CLASS: MECHANICAL PART; Manufacturer: PENCOM; Manufacturer PN: WA1021; PART_NUMBER: 762-0008
MP9-MP12 = BLANK_PINLESS_MECHANICAL_PART: SCREW, MACHINE,#4-40 X 1/2,PHILLIPS PH,SS; CLASS: MECHANICAL PART; Manufacturer: PENCOM; Manufacturer PN: SC3389; PART_NUMBER: 760-0065
MP13-MP16 = BLANK_PINLESS_MECHANICAL_PART: WASHER, LOCK,INT. TOOTH,#4,SS; CLASS: MECHANICAL PART; Manufacturer: PENCOM; Manufacturer PN: WA1196; PART_NUMBER: 762-0009
MP17-MP20 = BLANK_PINLESS_MECHANICAL_PART: NUT, HEX,#4-40,SS 18-8; CLASS: MECHANICAL PART; Manufacturer: PENCOM; Manufacturer PN: NU1043; PART_NUMBER: 761-0005
MP21-MP24 = BLANK_PINLESS_MECHANICAL_PART: BOLT, HEX TAP,5/16-24X1-1/4,SS; CLASS: MECHANICAL PART; Manufacturer: PENCOM; Manufacturer PN: BO2066; PART_NUMBER: 760-0068
MP25-MP32 = BLANK_PINLESS_MECHANICAL_PART: WASHER, FLAT,5/16,0.344ID, 0.688OD/0.065THK,SS; CLASS: MECHANICAL PART; Manufacturer: PENCOM; Manufacturer PN: WA2607; PART_NUMBER: 762-0014
MP33-MP36 = BLANK_PINLESS_MECHANICAL_PART: WASHER, INT. TOOTH LOCK,5/16, 0.326ID/0.602OD/0.031THK,SS; CLASS: MECHANICAL PART; Manufacturer: PENCOM; Manufacturer PN: WA4578; PART_NUMBER: 762-0015
MP37-MP40 = BLANK_PINLESS_MECHANICAL_PART: NUT, HEX,5/16-24,FIN-NU-SS; CLASS: MECHANICAL PART; Manufacturer: PENCOM; Manufacturer PN: NU3211; PART_NUMBER: 761-0008
PCB1 = BLANK_PCB_PART: BOM Notes: REV02; CLASS: PCB; Manufacturer: MAO BANG; Manufacturer PN: 600-DC2442A; PART_NUMBER: 600-DC2442A

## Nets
+5V: C14.1 E16.1(A) J1.2(VCCIO) J1.10(EEVCC) J2.1(AUXP) J2.5(LGKPWR) R10.1 R11.1 R12.1 R13.1 R14.1 R21.1 R22.1 U2.8(VCC)
GND_SIGNAL: C1.2 C2.2 C3.2 C4.2 C6.2 C7.2 C8.2 C11.1 C12.1 C13.2 C14.2 D1.1(CATHODE) D2.1(CATHODE) D3.2(A) D4.2(A) D5.1(CATHODE) D6.1(CATHODE) D7.1(CATHODE) D10.2(A) D11.2(A) D12.2(A) D13.2(A) E9.1(A) E10.1(A) E15.1(A) E17.1(A) E21.1 J1.3(GND) J1.8(GND) J1.12(EEGND) J1.13(GND) J2.3(GND) J2.10(GND) JP1.2 JP2.4 JP3.4 JP4.4 JP5.4 JP6.3 MTG1.1 Q3.2 Q4.2 Q5.2 R1.2 R8.2 R19.2 R20.2 R135.1 TP1.1 U1.3(GND) U1.20(KGND) U1.33(EXPOSED_PAD) U2.1(A0) U2.2(A1) U2.3(A2) U2.4(VSS) Y2.2(GND) Z1.2(A) Z2.2(A)
A: Q1.5(D) Q2.5(D) Q7.5(D) Q8.5(D) Q9.5(D) Q10.5(D) Q11.5(D) Q12.5(D) R24.1 R25.2 R27.1 R29.1 R30.2 R32.1 R34.1 R35.2 R37.1 R39.1 R41.2 R43.1 R44.1 R47.2 R49.1 R51.1 R52.1 R53.2 R56.1 R57.1 R58.2 R61.1 R62.1 R63.2 R78.1 R79.1 R80.2 R83.1 R84.1 R85.2 R88.1 R89.1 R90.2 R93.1 R94.1 R95.2 R98.1 R99.1 R100.2 R103.1 R104.1 R105.2 R108.1 R109.1 R110.2 R113.1 R114.1 R115.2
ADC+: R23.1 R28.1 R33.1 R38.1 R46.1 R54.1 R59.1 R64.1 R68.1 R133.1 TP4.1(P1) U1.30(ADC+)
ADC-: R24.2 R29.2 R34.2 R39.2 R44.2 R52.2 R57.2 R62.2 R67.2 R134.2 TP7.1(P1) U1.26(ADC-)
B: Q6.5(D) R66.1 R67.1 R69.2
GATE1: C10.1 E22.1(A) R74.2 R76.2 U1.23(GATE1)
GATE2: C9.1 E23.1(A) R70.1 R71.1 R72.1 R73.1 R75.2 R129.1 R130.1 R131.1 R132.1 U1.24(GATE2)
GPIO1: E3.1(A) R125.2 R127.2 U1.19(GPIO1)
GPIO2: D9.1(CATHODE) R16.1 R19.1 R126.2 U1.18(GPIO2)
GPIO3: D8.1(CATHODE) R15.1 R20.1 U1.17(GPIO3)
INPUT: C8.1 C15.2 D3.1(C) D4.1(C) D10.1(C) D11.1(C) D12.1(C) D13.1(C) E1.1 E6.1(A) R3.1 R4.2 R5.1 R6.1 R23.2 R25.1 R26.2 R28.2 R30.1 R31.2 R33.2 R35.1 R36.2 R38.2 R41.1 R42.2 R46.2 R47.1 R48.2 R50.2 R53.1 R54.2 R55.2 R58.1 R59.2 R60.2 R63.1 R64.2 R65.2 R68.2 R69.1 R77.2 R80.1 R81.2 R82.2 R85.1 R86.2 R87.2 R90.1 R91.2 R92.2 R95.1 R96.2 R97.2 R100.1 R101.2 R102.2 R105.1 R106.2 R107.2 R110.1 R111.2 R112.2 R115.1 R116.2 U1.31(VDD)
INTVCC: C6.1 E4.1(A) JP2.1 JP3.1 JP4.1 JP5.1 JP6.1 R9.1 U1.5(INTVCC)
SCL: E8.1(A) J1.4(SCK/SCL) J2.4(SCL) Q4.1 U1.14(SCL)
SDA: E11.1(A) J1.7(MOSI/SDA) J2.2(SDA) Q5.1 U1.12(SDAI) U1.13(SDAO)
SENSE+1: R65.1 TP5.1(P1) U1.29(SENSE+1)
SENSE+2: C5.1 R17.1 R26.1 R31.1 R36.1 R42.1 R45.1 R48.1 R50.1 R55.1 R60.1 TP3.1(P1) U1.28(SENSE+2)
SENSE-1: R66.2 R122.1 TP8.1(P1)
SENSE-2: R127.1 R128.2 TP6.1(P1) U1.25(SENSE-2)
SENSE-2_A: C5.2 R17.2 R27.2 R32.2 R37.2 R40.2 R43.2 R49.2 R51.2 R56.2 R61.2 R128.1
SOURCE: C1.1 C9.2 C10.2 E2.1 E5.1(A) Q1.1(S) Q1.2(S) Q1.3(S) Q2.1(S) Q2.2(S) Q2.3(S) Q6.1(S) Q6.2(S) Q6.3(S) Q7.1(S) Q7.2(S) Q7.3(S) Q8.1(S) Q8.2(S) Q8.3(S) Q9.1(S) Q9.2(S) Q9.3(S) Q10.1(S) Q10.2(S) Q10.3(S) Q11.1(S) Q11.2(S) Q11.3(S) Q12.1(S) Q12.2(S) Q12.3(S) R7.2 R18.1 U1.22(SOURCE)
N16359410: J1.9(EESDA) J2.12(AUXSDA) R13.2 U2.5(SDA)
N16362829: R14.2 TP2.1 U2.7(WP)
N16374572: D5.2(ANODE) Q3.3 R21.2
N16374891: D6.2(ANODE) Q4.3 R10.2
N16374930: D7.2(ANODE) Q5.3 R11.2
N18222437: R7.1 R8.1 U1.21(FB)
N18284784: JP5.2 JP5.3 U1.11(ADR2)
N18289049: JP4.2 JP4.3 U1.10(ADR1)
N18292359: JP3.2 JP3.3 U1.9(ADR0)
N18306085: JP6.2 U1.4(LOCK)
N18368024: C4.1 E7.1(A) JP2.2 JP2.3 R9.2 U1.1(ON)
N18459479: C3.1 JP1.1 U1.8(CLK_I) Y1.1 Y2.1
N18461854: C2.1 U1.7(CLK_O) Y1.2 Y2.3
N18667288: J1.11(EESCL) J2.11(AUXSCL) R12.2 U2.6(SCL)
N18704667: E12.1(A) Q3.1 R22.2 R123.2 R124.2 U1.15(~{ALERT})
N18712255: C13.1 E19.1(A) R2.1 R3.2 U1.32(UV)
N18712591: E20.1(A) R1.1 R2.2 U1.2(OV)
N18750723: C7.1 E18.1(A) U1.6(TIMER)
N19150519: E13.1(A) R16.2
N19152397: E14.1(A) R15.2
N20577435: R122.2 U1.27(SENSE-1)
N20972803: J2.7(GPIO_1) R125.1
N20976156: J2.9(OUTEN_1) R126.1
N21043579: D9.2(ANODE) R4.1 Z1.1(C)
N21809093: D8.2(ANODE) R6.2 Z2.1(C)
N22881125: D1.2(ANODE) R5.2
N22886736: D2.2(ANODE) R18.2
N23747318: J1.14(GPIO) R123.1
N23747809: J2.6(ALERTB) R124.1
N23939778: C11.2 R75.1
N23941696: C12.2 R76.1
N23941727: Q6.4(G) R74.1
N23969349: R40.1 R78.2 R83.2 R88.2 R93.2 R98.2 R103.2 R108.2 R113.2
N23969501: R79.2 R84.2 R89.2 R94.2 R99.2 R104.2 R109.2 R114.2 R134.1
N23978047: Q1.4(G) R72.2
N23978049: Q9.4(G) R71.2
N23978062: Q8.4(G) R70.2
N23979125: Q2.4(G) R73.2
N23989407: Q11.4(G) R130.2
N23989431: Q10.4(G) R131.2
N23989433: Q7.4(G) R129.2
N23989498: Q12.4(G) R132.2
N23991274: R45.2 R77.1 R82.1 R87.1 R92.1 R97.1 R102.1 R107.1 R112.1
N23991288: R81.1 R86.1 R91.1 R96.1 R101.1 R106.1 R111.1 R116.1 R133.2
N24230488: C15.1 R135.2

Not connected (* = marked no-connect by the designer): J1 1(VUNREG)* 5(MISO)* 6(CS)*; J2 8(OUTEN_0)*; JP1 3*; U1 16(NC)*

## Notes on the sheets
sheet 1
- PCA ADDITIONAL PARTS
sheet 2
- "RS1"
- SECONDARY SIDE
- TO TOP SIDE
- "Q1"
- SECONDARY SIDE
- FROM TOP SIDE
- FROM TOP SIDE
- TO TOP SIDE
- NOTE: ALL RESISTORS AND CAPACITORS THIS PAGE ARE SIZE 0402 U.O.N.
- FROM TOP SIDE
- FROM TOP SIDE
sheet 3
- +12V IN
- CONNECTIONS TO PAGES 2 AND 3
- +12V IN
- = HIGH-CURRENT CONNECTIONS
- +12V OUT
- +12V OUT
- 200 AMPS
- GPIO3
- GPIO2
- IN
- ON
- INTVCC
- ON
- (300K)
- OUT
- (SHORT PIN)
- OV
- UV
- FLOAT
- (0.1u)
- GND
- GND
- GPI01
- SDA
- GPI02
- SCL
- CLK
- GPI03
- INT
- ALERT
- EXT
- INT VCC
- EXT 5V
- TIMER
- GND
- GND
- ADR2
- ADR1
- ADR0
- WRITE PROTECT
- HIGH CURRENT HOT SWAP CONTROLLER
- GND
- H
- H
- Quik Eval
- TM
- LOCK
- UNLESS OTHERWISE NOTED:
- NC
- NC
- WRITE
- 1. ALL RESISTORS THIS PAGE ARE 1% 0603.
- L
- L
- 2. ALL CAPACITORS THIS PAGE ARE 0603.
- GND
- ALERT
- SCL
- SDA
- GND
- DC 1613
sheet 4
- "RS1"
- PRIMARY SIDE
- "Q1"
- PRIMARY SIDE
- GATE2
- TO BOTTOM SIDE
- NICHICON P/N UVR1E102MPD
- OR EQUIVALENT
- "Q2"
- PRIMARY SIDE
- OPT
- TO BOTTOM SIDE
- "RS2"
- NICHICON P/N UVR1E102MPD
- OR EQUIVALENT
- OPT
- PRIMARY SIDE
- GATE1
- SENSE+2
- ADC+
- ADC-
- SENSE-2
- NOTE: ALL RESISTORS AND CAPACITORS THIS PAGE ARE SIZE 0402 U.O.N.
- SENSE+1
- SENSE-1
- =HIGH CURRENT CONNECTIONS
